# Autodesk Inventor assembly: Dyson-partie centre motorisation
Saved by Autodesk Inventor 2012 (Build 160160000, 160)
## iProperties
Created: 2012-11
Part Number: Dyson-partie centre motorisation
Document SubType Name: Assembly
Designer: Administrateur
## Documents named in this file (1)
- F:\Dyson\SI\2_Présentation éleve\SW_AM01 complet\Composants importés\Dyson Air Multiplier-Assemblage final\Dyson-partie centre motorisation.iam
